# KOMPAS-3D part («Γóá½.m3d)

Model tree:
1. Эскиз:1
2. Операция выдавливания:1
     Расстояние 1 = 2; Расстояние 2 = 8.2
3. Смещенная плоскость:1
     Расстояние = 5
4. Эскиз:8
5. Операция выдавливания:4
     Расстояние 1 = 3; Расстояние 2 = 3
6. Эскиз:9
7. Вырезать элемент выдавливания:2
     Расстояние 1 = 2.5
8. Эскиз:10
9. Вырезать элемент выдавливания:3
     Расстояние 1 = 44.5869
10. Эскиз:11
11. Операция выдавливания:5
     Расстояние 1 = 0.5; Расстояние 2 = 30
12. Эскиз:23
13. Вырезать элемент выдавливания:8
     Расстояние 1 = 2.5
14. Эскиз:25
15. Вырезать элемент выдавливания:9
     Расстояние 1 = 57.2477
16. Эскиз:26
17. Операция выдавливания:13
     Расстояние 1 = 3; Расстояние 2 = 30
18. Эскиз:27
19. Операция выдавливания:14
     Расстояние 1 = 2.5; Расстояние 2 = 2.5
20. Эскиз:28
21. Вырезать элемент выдавливания:10
     Расстояние 1 = 57.25
22. Зеркальный массив:7  (with: Операция выдавливания:1, Операция выдавливания:4, Вырезать элемент выдавливания:2, Вырезать элемент выдавливания:3, Операция выдавливания:5, Вырезать элемент выдавливания:8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)  (labels: Экземпляр ( 1 ); Экземпляр ( 2 ))
23. Фаска:1
     Угол = 71.5651; Длина 1 = 1; Длина 2 = 3
24. Эскиз:29
25. Операция выдавливания:15
     Расстояние 1 = 1; Расстояние 2 = 1
26. Эскиз:30
27. Операция выдавливания:16
     Расстояние 1 = 1; Расстояние 2 = 1
28. Эскиз:31
29. Вырезать элемент выдавливания:11
     Расстояние 1 = 1
30. Эскиз:32
31. Операция выдавливания:17
     Расстояние 1 = 1; Расстояние 2 = 1
32. Скругление:49
     Радиус = 0.5
33. Скругление:50
     Радиус = 0.2
34. Скругление:51
     Радиус = 0.2
35. Скругление:52
     Радиус = 0.5
36. Скругление:53
     Радиус = 0.1
37. Скругление:54
     Радиус = 0.1
38. Скругление:55
     Радиус = 0.1
39. Скругление:56
     Радиус = 0.1
40. Скругление:57
     Радиус = 0.1
41. Скругление:58
     Радиус = 0.1

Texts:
  Сплав АЛ8  ГОСТ 1583-93
  Экземпляр ( 1 )
  Экземпляр ( 2 )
